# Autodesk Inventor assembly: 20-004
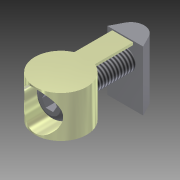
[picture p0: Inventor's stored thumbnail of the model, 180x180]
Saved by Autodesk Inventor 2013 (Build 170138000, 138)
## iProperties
Created: 2004-10
Part Number: 20-004
Document SubType Name: Assembly
Designer: Autodesk, Inc.
Manufacturer: Standard
Standards Organization: Custom
Description: UNIVERSAL FASTENER SET, 40 SERIES
Catalog Web Link: http://www.parker.com/ead/cm1.asp?cmid=809
Vendor: PARKER IPS
Mass: 43.7915 g
Surface Area: 46.6511 cm^2
Volume: 6.24866 cm^3
Density: 7.00814 g/cm^3
CAGE: 1LJX3
Dept. ID: Product Design
Description #2: ---
Finish #1: ---
Finish #2: ---
Material ID: ---
Project Number: ---
Author: Autodesk, Inc.
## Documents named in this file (7)
- Z:\_DATEN\Test Station\Components\20-004.iam
- Z:\_DATEN\Test Station\Components\20-004Z1.ipt
- Z:\_DATEN\Test Station\Components\24-130-8.ipt
- Z:\_DATEN\Test Station\Components\20-058.ipt
- C:\workfolder\Extra Samples\Models\Test Station\Library\Parker - IPS\Fastners\2X-YYY Universal Fastner.ipt
- C:\workfolder\Extra Samples\Models\Test Station\Library\Parker - IPS\Fastners\2X-YYY-ZZ IPS Screws.ipt
- C:\workfolder\Extra Samples\Models\Test Station\Library\Parker - IPS\Fastners\20-XXX TSlot Nuts.ipt
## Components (3 placed, 3 different names)
1. 20-004Z1:1 — Mate:1, Mate:2, Mate:4, Angle:1
2. 24-130-8:1 — Mate:1, Mate:2, Mate:3
3. 20-058:1 — Mate:3, Mate:4, Angle:1
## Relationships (5: Mate 4, Angle 1)
- Mate:1: 20-004Z1:1 ↔ 24-130-8:1
- Mate:2: 20-004Z1:1 ↔ 24-130-8:1
- Mate:3: 24-130-8:1 ↔ 20-058:1
- Mate:4: 20-004Z1:1 ↔ 20-058:1
- Angle:1: 20-004Z1:1 ↔ 20-058:1
